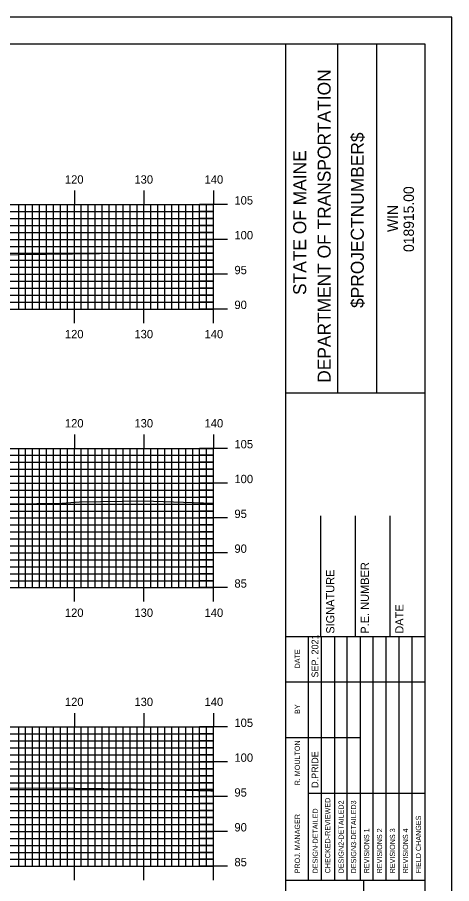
# Model space of a CAD drawing. Extents: x 1778319 to 1778662, y 442591 to 442811.
# Drawn here: x 1778596.1 to 1778658.5, y 442686.2 to 442810.5 of the extents above; entities that cross this region are included whole.
import ezdxf

# ---------------------------------------------------------------- set-up
doc = ezdxf.new("R2010")
doc.units = 0
for name, color, linetype in [('BORDER', 7, 'Continuous'), ('H_V ANNOTATION', 7, 'Continuous'), ('MAJOR', 7, 'Continuous'), ('MINOR', 7, 'Continuous'), ('PLOT BOUNDARY', 7, 'Continuous'), ('S_Roadway_Centerline', 7, 'Continuous')]:
    doc.layers.add(name, color=color, linetype=linetype)

msp = doc.modelspace()

# ---------------------------------------------------------------- linework, layer by layer
at = {"layer": 'BORDER'}
for p, q in [((1778634.7, 442596.67), (1778634.7, 442806.67)), ((1778642.16, 442756.66), (1778642.16, 442806.66)), ((1778647.75, 442756.66), (1778647.75, 442806.66)), ((1778634.7, 442756.65), (1778654.7, 442756.65)), ((1778639.7, 442721.67), (1778639.7, 442738.97)), ((1778644.7, 442721.67), (1778644.7, 442738.97)), ((1778649.7, 442721.67), (1778649.7, 442738.97)), ((1778634.7, 442721.67), (1778654.7, 442721.67)), ((1778634.7, 442686.67), (1778654.7, 442686.67)), ((1778645.89, 442616.67), (1778645.89, 442686.67))]:
    msp.add_line(p, q, dxfattribs=at)
msp.add_lwpolyline([(1778334.7, 442596.67), (1778654.7, 442596.67), (1778654.7, 442806.67), (1778334.7, 442806.67)], close=True, dxfattribs=at)
for points in [[(1778637.93, 442715.17), (1778637.93, 442721.67)], [(1778639.8, 442686.68), (1778639.8, 442721.67)], [(1778641.66, 442721.67), (1778641.66, 442686.68)], [(1778643.52, 442686.68), (1778643.52, 442721.67)], [(1778645.39, 442686.68), (1778645.39, 442721.67)], [(1778647.25, 442686.68), (1778647.25, 442721.67)], [(1778649.11, 442686.68), (1778649.11, 442721.67)], [(1778650.98, 442686.68), (1778650.98, 442721.67)], [(1778652.84, 442686.68), (1778652.84, 442721.67)], [(1778637.93, 442686.68), (1778637.93, 442720.26)], [(1778634.7, 442715.17), (1778654.7, 442715.17)], [(1778634.7, 442707.17), (1778637.93, 442707.17)], [(1778637.93, 442707.17), (1778645.39, 442707.17)], [(1778637.93, 442699.17), (1778654.7, 442699.17)]]:
    msp.add_lwpolyline(points, dxfattribs=at)
at = {"layer": 'MAJOR'}
for p, q in [((1778604.3, 442785.67), (1778604.3, 442783.67)), ((1778614.3, 442785.67), (1778614.3, 442783.67)), ((1778624.3, 442785.67), (1778624.3, 442783.67)), ((1778344.3, 442783.67), (1778624.3, 442783.67)), ((1778344.3, 442783.67), (1778624.3, 442783.67)), ((1778604.3, 442768.67), (1778604.3, 442783.67)), ((1778614.3, 442768.67), (1778614.3, 442783.67)), ((1778626.31, 442783.67), (1778622.3, 442783.67)), ((1778624.3, 442768.67), (1778624.3, 442783.67)), ((1778624.3, 442768.67), (1778624.3, 442783.67)), ((1778344.3, 442778.67), (1778624.3, 442778.67)), ((1778626.31, 442778.67), (1778622.3, 442778.67)), ((1778344.3, 442773.67), (1778624.3, 442773.67)), ((1778626.31, 442773.67), (1778622.3, 442773.67)), ((1778344.3, 442768.67), (1778624.3, 442768.67)), ((1778344.3, 442768.67), (1778624.3, 442768.67)), ((1778604.3, 442766.66), (1778604.3, 442768.67)), ((1778614.3, 442766.66), (1778614.3, 442768.67)), ((1778626.31, 442768.67), (1778622.3, 442768.67)), ((1778624.3, 442766.66), (1778624.3, 442768.67)), ((1778604.3, 442750.67), (1778604.3, 442748.67)), ((1778614.3, 442750.67), (1778614.3, 442748.67)), ((1778624.3, 442750.67), (1778624.3, 442748.67)), ((1778344.3, 442748.67), (1778624.3, 442748.67)), ((1778344.3, 442748.67), (1778624.3, 442748.67)), ((1778604.3, 442728.67), (1778604.3, 442748.67)), ((1778614.3, 442728.67), (1778614.3, 442748.67)), ((1778626.31, 442748.67), (1778622.3, 442748.67)), ((1778624.3, 442728.67), (1778624.3, 442748.67)), ((1778624.3, 442728.67), (1778624.3, 442748.67)), ((1778344.3, 442743.67), (1778624.3, 442743.67)), ((1778626.31, 442743.67), (1778622.3, 442743.67)), ((1778344.3, 442738.67), (1778624.3, 442738.67)), ((1778626.31, 442738.67), (1778622.3, 442738.67)), ((1778344.3, 442733.67), (1778624.3, 442733.67)), ((1778626.31, 442733.67), (1778622.3, 442733.67)), ((1778344.3, 442728.67), (1778624.3, 442728.67)), ((1778344.3, 442728.67), (1778624.3, 442728.67)), ((1778604.3, 442726.66), (1778604.3, 442728.67)), ((1778614.3, 442726.66), (1778614.3, 442728.67)), ((1778626.31, 442728.67), (1778622.3, 442728.67)), ((1778624.3, 442726.66), (1778624.3, 442728.67)), ((1778604.3, 442710.67), (1778604.3, 442708.67)), ((1778614.3, 442710.67), (1778614.3, 442708.67)), ((1778624.3, 442710.67), (1778624.3, 442708.67)), ((1778344.3, 442708.67), (1778624.3, 442708.67)), ((1778344.3, 442708.67), (1778624.3, 442708.67)), ((1778604.3, 442688.67), (1778604.3, 442708.67)), ((1778614.3, 442688.67), (1778614.3, 442708.67)), ((1778626.31, 442708.67), (1778622.3, 442708.67)), ((1778624.3, 442688.67), (1778624.3, 442708.67)), ((1778624.3, 442688.67), (1778624.3, 442708.67)), ((1778344.3, 442703.67), (1778624.3, 442703.67)), ((1778626.31, 442703.67), (1778622.3, 442703.67)), ((1778344.3, 442698.67), (1778624.3, 442698.67)), ((1778626.31, 442698.67), (1778622.3, 442698.67)), ((1778344.3, 442693.67), (1778624.3, 442693.67)), ((1778626.31, 442693.67), (1778622.3, 442693.67)), ((1778344.3, 442688.67), (1778624.3, 442688.67)), ((1778344.3, 442688.67), (1778624.3, 442688.67)), ((1778604.3, 442686.66), (1778604.3, 442688.67)), ((1778614.3, 442686.66), (1778614.3, 442688.67)), ((1778626.31, 442688.67), (1778622.3, 442688.67)), ((1778624.3, 442686.66), (1778624.3, 442688.67))]:
    msp.add_line(p, q, dxfattribs=at)
at = {"layer": 'MINOR'}
for p, q in [((1778596.3, 442768.67), (1778596.3, 442783.67)), ((1778597.3, 442768.67), (1778597.3, 442783.67)), ((1778598.3, 442768.67), (1778598.3, 442783.67)), ((1778599.3, 442768.67), (1778599.3, 442783.67)), ((1778600.3, 442768.67), (1778600.3, 442783.67)), ((1778601.3, 442768.67), (1778601.3, 442783.67)), ((1778602.3, 442768.67), (1778602.3, 442783.67)), ((1778603.3, 442768.67), (1778603.3, 442783.67)), ((1778605.3, 442768.67), (1778605.3, 442783.67)), ((1778606.3, 442768.67), (1778606.3, 442783.67)), ((1778607.3, 442768.67), (1778607.3, 442783.67)), ((1778608.3, 442768.67), (1778608.3, 442783.67)), ((1778609.3, 442768.67), (1778609.3, 442783.67)), ((1778610.3, 442768.67), (1778610.3, 442783.67)), ((1778611.3, 442768.67), (1778611.3, 442783.67)), ((1778612.3, 442768.67), (1778612.3, 442783.67)), ((1778613.3, 442768.67), (1778613.3, 442783.67)), ((1778615.3, 442768.67), (1778615.3, 442783.67)), ((1778616.3, 442768.67), (1778616.3, 442783.67)), ((1778617.3, 442768.67), (1778617.3, 442783.67)), ((1778618.3, 442768.67), (1778618.3, 442783.67)), ((1778619.3, 442768.67), (1778619.3, 442783.67)), ((1778620.3, 442768.67), (1778620.3, 442783.67)), ((1778621.3, 442768.67), (1778621.3, 442783.67)), ((1778622.3, 442768.67), (1778622.3, 442783.67)), ((1778623.3, 442768.67), (1778623.3, 442783.67)), ((1778344.3, 442782.67), (1778624.3, 442782.67)), ((1778344.3, 442781.67), (1778624.3, 442781.67)), ((1778624.3, 442782.67), (1778622.3, 442782.67)), ((1778624.3, 442781.67), (1778622.3, 442781.67)), ((1778344.3, 442780.67), (1778624.3, 442780.67)), ((1778624.3, 442780.67), (1778622.3, 442780.67)), ((1778344.3, 442779.67), (1778624.3, 442779.67)), ((1778624.3, 442779.67), (1778622.3, 442779.67)), ((1778344.3, 442777.67), (1778624.3, 442777.67)), ((1778624.3, 442777.67), (1778622.3, 442777.67)), ((1778344.3, 442776.67), (1778624.3, 442776.67)), ((1778344.3, 442775.67), (1778624.3, 442775.67)), ((1778624.3, 442776.67), (1778622.3, 442776.67)), ((1778624.3, 442775.67), (1778622.3, 442775.67)), ((1778344.3, 442774.67), (1778624.3, 442774.67)), ((1778624.3, 442774.67), (1778622.3, 442774.67)), ((1778344.3, 442772.67), (1778624.3, 442772.67)), ((1778624.3, 442772.67), (1778622.3, 442772.67)), ((1778344.3, 442771.67), (1778624.3, 442771.67)), ((1778344.3, 442770.67), (1778624.3, 442770.67)), ((1778624.3, 442771.67), (1778622.3, 442771.67)), ((1778624.3, 442770.67), (1778622.3, 442770.67)), ((1778344.3, 442769.67), (1778624.3, 442769.67)), ((1778624.3, 442769.67), (1778622.3, 442769.67)), ((1778596.3, 442728.67), (1778596.3, 442748.67)), ((1778597.3, 442728.67), (1778597.3, 442748.67)), ((1778598.3, 442728.67), (1778598.3, 442748.67)), ((1778599.3, 442728.67), (1778599.3, 442748.67)), ((1778600.3, 442728.67), (1778600.3, 442748.67)), ((1778601.3, 442728.67), (1778601.3, 442748.67)), ((1778602.3, 442728.67), (1778602.3, 442748.67)), ((1778603.3, 442728.67), (1778603.3, 442748.67)), ((1778605.3, 442728.67), (1778605.3, 442748.67)), ((1778606.3, 442728.67), (1778606.3, 442748.67)), ((1778607.3, 442728.67), (1778607.3, 442748.67)), ((1778608.3, 442728.67), (1778608.3, 442748.67)), ((1778609.3, 442728.67), (1778609.3, 442748.67)), ((1778610.3, 442728.67), (1778610.3, 442748.67)), ((1778611.3, 442728.67), (1778611.3, 442748.67)), ((1778612.3, 442728.67), (1778612.3, 442748.67)), ((1778613.3, 442728.67), (1778613.3, 442748.67)), ((1778615.3, 442728.67), (1778615.3, 442748.67)), ((1778616.3, 442728.67), (1778616.3, 442748.67)), ((1778617.3, 442728.67), (1778617.3, 442748.67)), ((1778618.3, 442728.67), (1778618.3, 442748.67)), ((1778619.3, 442728.67), (1778619.3, 442748.67)), ((1778620.3, 442728.67), (1778620.3, 442748.67)), ((1778621.3, 442728.67), (1778621.3, 442748.67)), ((1778622.3, 442728.67), (1778622.3, 442748.67)), ((1778623.3, 442728.67), (1778623.3, 442748.67)), ((1778344.3, 442747.67), (1778624.3, 442747.67)), ((1778624.3, 442747.67), (1778622.3, 442747.67)), ((1778344.3, 442746.67), (1778624.3, 442746.67)), ((1778344.3, 442745.67), (1778624.3, 442745.67)), ((1778624.3, 442746.67), (1778622.3, 442746.67)), ((1778624.3, 442745.67), (1778622.3, 442745.67)), ((1778344.3, 442744.67), (1778624.3, 442744.67)), ((1778624.3, 442744.67), (1778622.3, 442744.67)), ((1778344.3, 442742.67), (1778624.3, 442742.67)), ((1778624.3, 442742.67), (1778622.3, 442742.67)), ((1778344.3, 442741.67), (1778624.3, 442741.67)), ((1778344.3, 442740.67), (1778624.3, 442740.67)), ((1778624.3, 442741.67), (1778622.3, 442741.67)), ((1778624.3, 442740.67), (1778622.3, 442740.67)), ((1778344.3, 442739.67), (1778624.3, 442739.67)), ((1778624.3, 442739.67), (1778622.3, 442739.67)), ((1778344.3, 442737.67), (1778624.3, 442737.67)), ((1778624.3, 442737.67), (1778622.3, 442737.67)), ((1778344.3, 442736.67), (1778624.3, 442736.67)), ((1778344.3, 442735.67), (1778624.3, 442735.67)), ((1778624.3, 442736.67), (1778622.3, 442736.67)), ((1778624.3, 442735.67), (1778622.3, 442735.67)), ((1778344.3, 442734.67), (1778624.3, 442734.67)), ((1778624.3, 442734.67), (1778622.3, 442734.67)), ((1778344.3, 442732.67), (1778624.3, 442732.67)), ((1778624.3, 442732.67), (1778622.3, 442732.67)), ((1778344.3, 442731.67), (1778624.3, 442731.67)), ((1778344.3, 442730.67), (1778624.3, 442730.67)), ((1778624.3, 442731.67), (1778622.3, 442731.67)), ((1778624.3, 442730.67), (1778622.3, 442730.67)), ((1778344.3, 442729.67), (1778624.3, 442729.67)), ((1778624.3, 442729.67), (1778622.3, 442729.67)), ((1778596.3, 442688.67), (1778596.3, 442708.67)), ((1778597.3, 442688.67), (1778597.3, 442708.67)), ((1778598.3, 442688.67), (1778598.3, 442708.67)), ((1778599.3, 442688.67), (1778599.3, 442708.67)), ((1778600.3, 442688.67), (1778600.3, 442708.67)), ((1778601.3, 442688.67), (1778601.3, 442708.67)), ((1778602.3, 442688.67), (1778602.3, 442708.67)), ((1778603.3, 442688.67), (1778603.3, 442708.67)), ((1778605.3, 442688.67), (1778605.3, 442708.67)), ((1778606.3, 442688.67), (1778606.3, 442708.67)), ((1778607.3, 442688.67), (1778607.3, 442708.67)), ((1778608.3, 442688.67), (1778608.3, 442708.67)), ((1778609.3, 442688.67), (1778609.3, 442708.67)), ((1778610.3, 442688.67), (1778610.3, 442708.67)), ((1778611.3, 442688.67), (1778611.3, 442708.67)), ((1778612.3, 442688.67), (1778612.3, 442708.67)), ((1778613.3, 442688.67), (1778613.3, 442708.67)), ((1778615.3, 442688.67), (1778615.3, 442708.67)), ((1778616.3, 442688.67), (1778616.3, 442708.67)), ((1778617.3, 442688.67), (1778617.3, 442708.67)), ((1778618.3, 442688.67), (1778618.3, 442708.67)), ((1778619.3, 442688.67), (1778619.3, 442708.67)), ((1778620.3, 442688.67), (1778620.3, 442708.67)), ((1778621.3, 442688.67), (1778621.3, 442708.67)), ((1778622.3, 442688.67), (1778622.3, 442708.67)), ((1778623.3, 442688.67), (1778623.3, 442708.67)), ((1778344.3, 442707.67), (1778624.3, 442707.67)), ((1778624.3, 442707.67), (1778622.3, 442707.67)), ((1778344.3, 442706.67), (1778624.3, 442706.67)), ((1778624.3, 442706.67), (1778622.3, 442706.67)), ((1778344.3, 442705.67), (1778624.3, 442705.67)), ((1778344.3, 442704.67), (1778624.3, 442704.67)), ((1778624.3, 442705.67), (1778622.3, 442705.67)), ((1778624.3, 442704.67), (1778622.3, 442704.67)), ((1778344.3, 442702.67), (1778624.3, 442702.67)), ((1778624.3, 442702.67), (1778622.3, 442702.67)), ((1778344.3, 442701.67), (1778624.3, 442701.67)), ((1778624.3, 442701.67), (1778622.3, 442701.67)), ((1778344.3, 442700.67), (1778624.3, 442700.67)), ((1778344.3, 442699.67), (1778624.3, 442699.67)), ((1778624.3, 442700.67), (1778622.3, 442700.67)), ((1778624.3, 442699.67), (1778622.3, 442699.67)), ((1778344.3, 442697.67), (1778624.3, 442697.67)), ((1778624.3, 442697.67), (1778622.3, 442697.67)), ((1778344.3, 442696.67), (1778624.3, 442696.67)), ((1778624.3, 442696.67), (1778622.3, 442696.67)), ((1778344.3, 442695.67), (1778624.3, 442695.67)), ((1778344.3, 442694.67), (1778624.3, 442694.67)), ((1778624.3, 442695.67), (1778622.3, 442695.67)), ((1778624.3, 442694.67), (1778622.3, 442694.67)), ((1778344.3, 442692.67), (1778624.3, 442692.67)), ((1778624.3, 442692.67), (1778622.3, 442692.67)), ((1778344.3, 442691.67), (1778624.3, 442691.67)), ((1778624.3, 442691.67), (1778622.3, 442691.67)), ((1778344.3, 442690.67), (1778624.3, 442690.67)), ((1778344.3, 442689.67), (1778624.3, 442689.67)), ((1778624.3, 442690.67), (1778622.3, 442690.67)), ((1778624.3, 442689.67), (1778622.3, 442689.67))]:
    msp.add_line(p, q, dxfattribs=at)
at = {"layer": 'PLOT BOUNDARY'}
msp.add_lwpolyline([(1778318.52, 442590.55), (1778658.52, 442590.55), (1778658.52, 442810.55), (1778318.52, 442810.55)], close=True, dxfattribs=at)
at = {"layer": 'S_Roadway_Centerline'}
for points in [[(1778528.07, 442776.01), (1778538.8, 442776.13), (1778551.87, 442776), (1778556.86, 442775.88), (1778561.83, 442776.07), (1778567.78, 442776.24), (1778574.21, 442776.16), (1778580.55, 442776.07), (1778586.85, 442776.22), (1778596.28, 442776.52), (1778611.8, 442776.7), (1778614.97, 442776.71), (1778618.4, 442776.67), (1778624.3, 442776.67)], [(1778530.49, 442740.05), (1778535.14, 442740.07), (1778554.16, 442739.94), (1778556.52, 442739.99), (1778559.16, 442739.98), (1778578.87, 442740.6), (1778598.92, 442740.73), (1778601.89, 442740.76), (1778605.03, 442740.97), (1778614.23, 442741.14), (1778624.3, 442740.8)], [(1778512.92, 442698.95), (1778532.18, 442699), (1778543.16, 442699.23), (1778556.26, 442699.3), (1778567.01, 442699.15), (1778576.41, 442698.8), (1778577.1, 442698.83), (1778589.45, 442699.9), (1778600.34, 442699.95), (1778612.59, 442699.79), (1778623.89, 442699.48), (1778624.3, 442699.48)]]:
    msp.add_lwpolyline(points, dxfattribs=at)

# ---------------------------------------------------------------- texts
at = {"layer": 'BORDER'}
for s, height, p in [('DEPARTMENT OF TRANSPORTATION', 1.8635, (1778641.12, 442758.08)), ('$PROJECTNUMBER$', 1.8635, (1778645.89, 442768.82)), ('STATE OF MAINE', 1.8635, (1778637.61, 442770.69)), ('018915.00', 1.491, (1778653.09, 442776.86)), ('WIN', 1.491, (1778650.78, 442779.73)), ('P.E. NUMBER', 1.1811, (1778646.62, 442722.06)), ('SIGNATURE', 1.181, (1778641.66, 442722.06)), ('DATE', 1.181, (1778651.59, 442722.06)), ('SEP. 2021', 0.969, (1778639.35, 442715.76)), ('DATE', 0.743, (1778636.71, 442717.08)), ('BY', 0.743, (1778636.71, 442710.54)), ('R. MOULTON', 0.745, (1778636.71, 442700.28)), ('D.PRIDE', 0.969, (1778639.35, 442699.92)), ('CHECKED-REVIEWED', 0.7455, (1778641.07, 442687.65)), ('DESIGN2-DETAILED2', 0.7455, (1778643, 442687.65)), ('DESIGN3-DETAILED3', 0.7455, (1778644.79, 442687.65)), ('PROJ. MANAGER', 0.7455, (1778636.71, 442687.65)), ('DESIGN-DETAILED', 0.7455, (1778639.28, 442687.65)), ('FIELD CHANGES', 0.7455, (1778654.11, 442687.65)), ('REVISIONS 1', 0.7455, (1778646.66, 442687.65)), ('REVISIONS 2', 0.7455, (1778648.52, 442687.65)), ('REVISIONS 3', 0.7455, (1778650.38, 442687.65)), ('REVISIONS 4', 0.7455, (1778652.25, 442687.65))]:
    msp.add_text(s, height=height, rotation=90, dxfattribs=at).set_placement(p)
at = {"layer": 'H_V ANNOTATION'}
for s, p in [('120', (1778602.94, 442786.67)), ('130', (1778612.93, 442786.67)), ('140', (1778623.01, 442786.67)), ('105', (1778627.3, 442783.67)), ('100', (1778627.3, 442778.67)), ('95', (1778627.3, 442773.67)), ('90', (1778627.3, 442768.67)), ('120', (1778602.94, 442764.47)), ('130', (1778612.93, 442764.47)), ('140', (1778623.01, 442764.47)), ('120', (1778602.94, 442751.67)), ('130', (1778612.93, 442751.67)), ('140', (1778623.01, 442751.67)), ('105', (1778627.3, 442748.67)), ('100', (1778627.3, 442743.67)), ('95', (1778627.3, 442738.67)), ('90', (1778627.3, 442733.67)), ('85', (1778627.3, 442728.67)), ('120', (1778602.94, 442724.47)), ('130', (1778612.93, 442724.47)), ('140', (1778623.01, 442724.47)), ('120', (1778602.94, 442711.67)), ('130', (1778612.93, 442711.67)), ('140', (1778623.01, 442711.67)), ('105', (1778627.3, 442708.67)), ('100', (1778627.3, 442703.67)), ('95', (1778627.3, 442698.67)), ('90', (1778627.3, 442693.67)), ('85', (1778627.3, 442688.67))]:
    msp.add_text(s, height=1.2, dxfattribs=at).set_placement(p)

doc.saveas('drawing.dxf')
